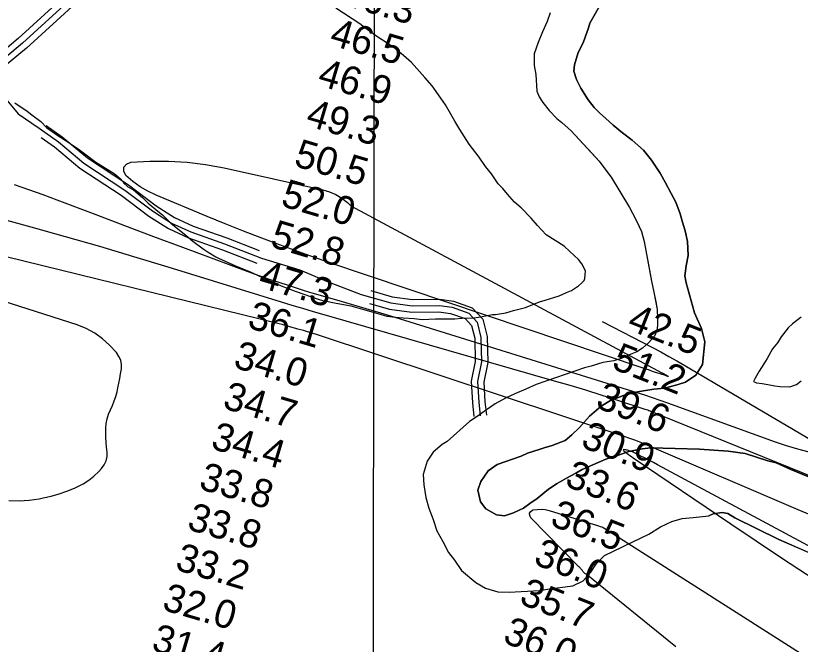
# Model space of a CAD drawing. Extents: x 3192986 to 3230865, y 867483 to 892886.
# Drawn here: x 3212034 to 3213899, y 880283 to 881777 of the extents above; entities that cross this region are included whole.
import ezdxf

# ---------------------------------------------------------------- set-up
doc = ezdxf.new("R2010")
doc.units = 0
for name, color, linetype in [('V-GRID-MAJR', 7, 'Continuous'), ('V-RIVR-RANG', 7, 'Continuous'), ('V-ROAD-CNTR', 7, 'Continuous'), ('V-SITE-VEGE', 7, 'Continuous'), ('V-TOPO-MAJR', 7, 'Continuous'), ('V-TOPO-MINR', 7, 'Continuous'), ('V-TOPO-SHOR', 7, 'Continuous')]:
    doc.layers.add(name, color=color, linetype=linetype)

msp = doc.modelspace()

# ---------------------------------------------------------------- linework, layer by layer
at = {"layer": 'V-GRID-MAJR'}
msp.add_spline([(3212870.4, 872891.2), (3212881.9, 878950.4), (3212893.3, 885013.1), (3212904.8, 891075.8), (3212904.8, 891079.2)], degree=3, dxfattribs=at)
at = {"layer": 'V-ROAD-CNTR'}
for points in [[(3212546.2, 882171.5), (3212450.8, 882086.8), (3212324.9, 881977.5), (3212156.6, 881829.2), (3212040.1, 881722.5), (3211954.9, 881651.4), (3211923.3, 881628.9)], [(3212166.6, 881818.1), (3212049.9, 881711.2), (3211964.1, 881639.5), (3211897.6, 881592.2), (3211798.6, 881545.3), (3211684.7, 881510.3), (3211599.3, 881496.3), (3211553.9, 881489.8), (3211525.1, 881494.2), (3211518, 881509.3), (3211515.9, 881530.1), (3211524.6, 881534.2), (3211547.8, 881535.8), (3211573.7, 881526.2), (3211590.7, 881514.1), (3211603.3, 881507), (3211620.1, 881498.4)], [(3212176.7, 881806.9), (3212059.8, 881699.9), (3212000.6, 881650.5)], [(3212013.3, 881576.2), (3212039.6, 881543.7), (3212089.7, 881509.4), (3212135.6, 881477.1), (3212195.9, 881426.7), (3212293.2, 881362.4), (3212359.3, 881313.1), (3212404.3, 881284.1), (3212450.4, 881263), (3212530.6, 881234.6), (3212618.5, 881200.7), (3212709.2, 881172.7), (3212772.6, 881145.7), (3212855, 881114.7), (3212925.6, 881094.5), (3212976.5, 881087.5), (3213041.2, 881088.4), (3213071.2, 881084), (3213110.8, 881070), (3213131, 881048.5), (3213140, 881012.3), (3213141.1, 880954.2), (3213131.9, 880907.3), (3213134.6, 880858.4), (3213138.2, 880825.9)], [(3212106.4, 881515.9), (3212144.7, 881489), (3212204.9, 881438.8), (3212301.8, 881374.6), (3212367.8, 881325.4), (3212411.6, 881297.3), (3212456.1, 881277), (3212535.8, 881248.7), (3212612.8, 881218.9)], [(3212094.5, 881487.6), (3212126.5, 881465.1), (3212186.9, 881414.7), (3212284.6, 881350.1), (3212350.7, 881300.8), (3212397.1, 881270.9), (3212444.8, 881249.1), (3212525.3, 881220.6), (3212607.6, 881188.8)], [(3212878.4, 881123.6), (3212928.7, 881109.2), (3212977.5, 881102.5), (3213042.2, 881103.4), (3213074.8, 881098.7), (3213119.2, 881082.9), (3213144.6, 881056), (3213154.9, 881014.3), (3213156.2, 880952.9), (3213147, 880906.3), (3213149.5, 880859.7), (3213153.1, 880827.6)], [(3212875.2, 881093.3), (3212922.5, 881079.8), (3212975.6, 881072.5), (3213040.2, 881073.4), (3213067.6, 881069.4), (3213102.3, 881057), (3213117.4, 881041.1), (3213125, 881010.3), (3213126.1, 880955.5), (3213116.8, 880908.4), (3213119.6, 880857.2), (3213123.2, 880824.3)]]:
    msp.add_lwpolyline(points, dxfattribs=at)
at = {"layer": 'V-SITE-VEGE'}
for p, q in [((3212852, 881757.4), (3212795, 881794.9)), ((3213304.2, 881783.7), (3213297.2, 881762.6)), ((3212869.7, 881743.9), (3212852, 881757.4)), ((3213297.2, 881762.6), (3213286.2, 881738.3)), ((3212894.8, 881725.7), (3212869.7, 881743.9)), ((3213286.2, 881738.3), (3213275.9, 881712.8)), ((3212912.6, 881715), (3212894.8, 881725.7)), ((3212936.8, 881697.7), (3212912.6, 881715)), ((3213275.9, 881712.8), (3213266.8, 881686.1)), ((3212955.5, 881682.4), (3212936.8, 881697.7)), ((3212975, 881665.2), (3212955.5, 881682.4)), ((3213266.8, 881686.1), (3213266.6, 881658.5)), ((3213006.5, 881629.8), (3212975, 881665.2)), ((3213266.6, 881658.5), (3213270.2, 881637.4)), ((3213270.2, 881637.4), (3213273.1, 881597.3)), ((3213024.2, 881609.8), (3213006.5, 881629.8)), ((3213044.5, 881581.2), (3213024.2, 881609.8)), ((3213055.6, 881565.1), (3213044.5, 881581.2)), ((3213273.1, 881597.3), (3213278.4, 881583.9)), ((3213278.4, 881583.9), (3213287.2, 881570.4)), ((3212032.3, 881569.4), (3212061.3, 881550.1)), ((3213077.6, 881526.1), (3213055.6, 881565.1)), ((3213287.2, 881570.4), (3213302.1, 881551.9)), ((3212061.3, 881550.1), (3212072.4, 881541.5)), ((3213302.1, 881551.9), (3213320.5, 881532.8)), ((3212072.4, 881541.5), (3212093.9, 881525.2)), ((3212093.9, 881525.2), (3212106.9, 881510.8)), ((3213089.6, 881506.2), (3213077.6, 881526.1)), ((3213320.5, 881532.8), (3213332.1, 881523.2)), ((3213332.1, 881523.2), (3213354, 881503.5)), ((3212106.9, 881510.8), (3212132.1, 881493.5)), ((3213111.7, 881471.9), (3213089.6, 881506.2)), ((3212132.1, 881493.5), (3212151.7, 881481)), ((3213354, 881503.5), (3213421, 881431.2)), ((3212151.7, 881481), (3212182.5, 881460.8)), ((3213135.7, 881440.5), (3213111.7, 881471.9)), ((3212182.5, 881460.8), (3212198.3, 881448.3)), ((3212198.3, 881448.3), (3212224.4, 881429.1)), ((3213150.5, 881418.6), (3213135.7, 881440.5)), ((3213421, 881431.2), (3213434.2, 881412.9)), ((3212224.4, 881429.1), (3212241.2, 881418.4)), ((3212241.2, 881418.4), (3212268.3, 881402)), ((3213165.3, 881401.4), (3213150.5, 881418.6)), ((3213434.2, 881412.9), (3213449.5, 881393.2)), ((3212268.3, 881402), (3212282.3, 881389.6)), ((3213181, 881377.6), (3213165.3, 881401.4)), ((3213449.5, 881393.2), (3213493, 881321.4)), ((3212282.3, 881389.6), (3212288.8, 881382.9)), ((3212288.8, 881382.9), (3212290.6, 881380)), ((3212290.6, 881380), (3212300.8, 881370.5)), ((3213192.1, 881366.2), (3213181, 881377.6)), ((3212300.8, 881370.5), (3212313.9, 881362.8)), ((3212313.9, 881362.8), (3212335.3, 881344.5)), ((3213203.3, 881352.8), (3213192.1, 881366.2)), ((3212335.3, 881344.5), (3212349.3, 881331.2)), ((3213220, 881333.7), (3213203.3, 881352.8)), ((3212349.3, 881331.2), (3212371.6, 881312)), ((3213235.8, 881320.3), (3213220, 881333.7)), ((3213259, 881295.5), (3213235.8, 881320.3)), ((3213493, 881321.4), (3213500.5, 881307.4)), ((3212371.6, 881312), (3212382.8, 881303.3)), ((3212382.8, 881303.3), (3212403.2, 881284.2)), ((3213500.5, 881307.4), (3213510.4, 881288.1)), ((3212403.2, 881284.2), (3212439.6, 881254.5)), ((3213274.7, 881278.3), (3213259, 881295.5)), ((3213510.4, 881288.1), (3213521.3, 881264.1)), ((3213295.2, 881256.3), (3213274.7, 881278.3)), ((3213521.3, 881264.1), (3213528.2, 881240.3)), ((3212439.6, 881254.5), (3212455.4, 881241.1)), ((3213338.1, 881229.3), (3213295.2, 881256.3)), ((3212455.4, 881241.1), (3212479.6, 881222.8)), ((3213351.1, 881216.9), (3213338.1, 881229.3)), ((3213528.2, 881240.3), (3213545.6, 881146.4)), ((3212479.6, 881222.8), (3212491.8, 881215.1)), ((3212491.8, 881215.1), (3212509.5, 881203.5)), ((3213371.6, 881197.8), (3213351.1, 881216.9)), ((3212509.5, 881203.5), (3212516.1, 881200.6)), ((3212516.1, 881200.6), (3212556.3, 881182.1)), ((3213379.9, 881187.3), (3213371.6, 881197.8)), ((3212556.3, 881182.1), (3212591, 881168.4)), ((3213388.2, 881170.2), (3213379.9, 881187.3)), ((3213388, 881160.8), (3213388.2, 881170.2)), ((3212591, 881168.4), (3212619.1, 881155.8)), ((3212619.1, 881155.8), (3212664.9, 881135.3)), ((3213385, 881147.6), (3213387, 881152.3)), ((3213387, 881152.3), (3213388, 881160.8)), ((3212664.9, 881135.3), (3212698.7, 881122.6)), ((3213355.4, 881123.6), (3213371.6, 881134.6)), ((3213371.6, 881134.6), (3213379.3, 881141.1)), ((3213379.3, 881141.1), (3213385, 881147.6)), ((3213545.6, 881146.4), (3213551.2, 881119.7)), ((3212698.7, 881122.6), (3212737.1, 881108.9)), ((3213326.1, 881110.8), (3213343.1, 881119)), ((3213343.1, 881119), (3213355.4, 881123.6)), ((3213551.2, 881119.7), (3213559.1, 881079.1)), ((3212737.1, 881108.9), (3212753.1, 881103)), ((3212753.1, 881103), (3212763.4, 881100)), ((3212763.4, 881100), (3212772.8, 881098.9)), ((3212772.8, 881098.9), (3212791.6, 881094.9)), ((3212791.6, 881094.9), (3212831, 881087.7)), ((3213245.6, 881083.7), (3213278.7, 881097.3)), ((3213278.7, 881097.3), (3213292.9, 881100.9)), ((3213292.9, 881100.9), (3213312.8, 881107.2)), ((3213312.8, 881107.2), (3213326.1, 881110.8)), ((3212831, 881087.7), (3212858.2, 881079.8)), ((3212858.2, 881079.8), (3212894.8, 881068.9)), ((3213199.2, 881071.1), (3213217.2, 881076.5)), ((3213217.2, 881076.5), (3213245.6, 881083.7)), ((3213559.1, 881079.1), (3213559.5, 881057.2)), ((3212894.8, 881068.9), (3212916.4, 881063)), ((3212916.4, 881063), (3212937.1, 881060.8)), ((3212937.1, 881060.8), (3212955, 881058.6)), ((3212955, 881058.6), (3212981.4, 881057.3)), ((3212981.4, 881057.3), (3213000.2, 881055.2)), ((3213051.1, 881056.3), (3213077.5, 881056.9)), ((3213077.5, 881056.9), (3213094.5, 881058.5)), ((3213094.5, 881058.5), (3213123.7, 881059)), ((3213123.7, 881059), (3213138.8, 881061.6)), ((3213138.8, 881061.6), (3213167.1, 881066.9)), ((3213167.1, 881066.9), (3213174.7, 881066.8)), ((3213174.7, 881066.8), (3213199.2, 881071.1)), ((3213559.5, 881057.2), (3213559.2, 881041.7)), ((3213000.2, 881055.2), (3213032.2, 881056.6)), ((3213032.2, 881056.6), (3213051.1, 881056.3)), ((3213559.2, 881041.7), (3213557.6, 881028.4)), ((3213557.6, 881028.4), (3213552.2, 881015.2)), ((3213552.2, 881015.2), (3213539, 881000)), ((3213524, 880986.5), (3213510.1, 880978.4)), ((3213539, 881000), (3213524, 880986.5)), ((3213490.4, 880970.1), (3213473.2, 880962.4)), ((3213510.1, 880978.4), (3213490.4, 880970.1)), ((3213429.8, 880952.9), (3213401.6, 880943.8)), ((3213455.8, 880957.1), (3213429.8, 880952.9)), ((3213473.2, 880962.4), (3213455.8, 880957.1)), ((3213386.2, 880940.2), (3213271.3, 880900.5)), ((3213401.6, 880943.8), (3213386.2, 880940.2)), ((3213246.6, 880889.3), (3213220.8, 880878.6)), ((3213271.3, 880900.5), (3213246.6, 880889.3)), ((3213220.8, 880878.6), (3213198.6, 880868)), ((3213173.4, 880854.8), (3213153.1, 880840.1)), ((3213198.6, 880868), (3213173.4, 880854.8)), ((3213153.1, 880840.1), (3213131.1, 880824.8)), ((3213131.1, 880824.8), (3213112.4, 880812.9)), ((3213112.4, 880812.9), (3213059.6, 880765.1)), ((3213059.6, 880765.1), (3213048.1, 880758.1)), ((3213048.1, 880758.1), (3213026.1, 880739.6)), ((3213026.1, 880739.6), (3213012.3, 880718.2)), ((3213012.3, 880718.2), (3213002.8, 880686.5)), ((3213002.8, 880686.5), (3213004.1, 880661.9)), ((3213004.1, 880661.9), (3213008.7, 880632.3)), ((3213008.7, 880632.3), (3213016.1, 880607.1)), ((3213016.1, 880607.1), (3213026.3, 880580.1)), ((3213681.2, 880588.4), (3213691.9, 880593.4)), ((3213691.9, 880593.4), (3213713.1, 880596.1)), ((3213713.1, 880596.1), (3213726.4, 880594.1)), ((3213726.4, 880594.1), (3213743.7, 880583.9)), ((3213026.3, 880580.1), (3213034.9, 880552.5)), ((3213566.8, 880562.2), (3213593.6, 880575.4)), ((3213593.6, 880575.4), (3213618.1, 880582)), ((3213618.1, 880582), (3213644.4, 880584.5)), ((3213644.4, 880584.5), (3213681.2, 880588.4)), ((3213743.7, 880583.9), (3213847.8, 880532.4)), ((3213539, 880545), (3213566.8, 880562.2)), ((3213034.9, 880552.5), (3213049.5, 880527.5)), ((3213433.9, 880494.2), (3213520.8, 880536)), ((3213520.8, 880536), (3213539, 880545)), ((3213049.5, 880527.5), (3213063, 880501.7)), ((3213847.8, 880532.4), (3213989.3, 880470.5)), ((3213063, 880501.7), (3213076.9, 880483.2)), ((3213076.9, 880483.2), (3213094, 880459)), ((3213414.4, 880475.1), (3213433.9, 880494.2)), ((3213401.1, 880454.5), (3213414.4, 880475.1)), ((3213094, 880459), (3213127.5, 880429.9)), ((3213383, 880434.4), (3213401.1, 880454.5)), ((3213127.5, 880429.9), (3213150.9, 880416.5)), ((3213358.1, 880422.2), (3213383, 880434.4)), ((3213150.9, 880416.5), (3213179.8, 880408.3)), ((3213179.8, 880408.3), (3213207.2, 880407.2)), ((3213207.2, 880407.2), (3213279, 880410.9)), ((3213279, 880410.9), (3213302.8, 880414.7)), ((3213302.8, 880414.7), (3213327.1, 880418.2)), ((3213327.1, 880418.2), (3213358.1, 880422.2))]:
    msp.add_line(p, q, dxfattribs=at)
for points in [[(3213430.9, 881816.5), (3213398.9, 881759.4), (3213395.5, 881748.2), (3213382.6, 881712), (3213370.7, 881689.4), (3213362.3, 881659.9), (3213360.9, 881645.1), (3213367, 881625.5), (3213377.1, 881604.5), (3213394.7, 881576.7), (3213409.2, 881558.5), (3213422.2, 881545.1), (3213436, 881533.3), (3213454.2, 881517), (3213476.7, 881498.3), (3213499.7, 881480.8), (3213526.5, 881457.2), (3213545.4, 881433.7), (3213565.7, 881402.6), (3213578.6, 881379.7), (3213592.2, 881354.3), (3213603.2, 881333.7), (3213613.2, 881306.4), (3213619.3, 881286.3), (3213625, 881265.4), (3213630.6, 881240.1), (3213632.5, 881207.3), (3213627.8, 881182.2), (3213624.6, 881159), (3213628, 881141.8), (3213647.8, 881070.7), (3213664.4, 881033.3), (3213672.4, 881001.6), (3213666.4, 880948.1), (3213650.4, 880922.7), (3213626.2, 880906.3), (3213608.5, 880900.5), (3213576.4, 880892.2)], [(3213901.4, 881060.3), (3213894, 881054.8), (3213880.1, 881044.9), (3213869.8, 881035), (3213853.9, 881014.1), (3213844.5, 880999.5), (3213833.3, 880985), (3213820.1, 880962.2), (3213812.6, 880949.5), (3213801.3, 880932.2), (3213794.7, 880921.2), (3213791, 880914), (3213788.1, 880907.6), (3213794.5, 880904.7), (3213808.2, 880902.7), (3213830.2, 880898.7), (3213838.5, 880897.7), (3213850.4, 880895.7), (3213874.3, 880895.3), (3213890, 880900.6), (3213901.1, 880909.6)], [(3213576.4, 880892.2), (3213550.8, 880889.4), (3213517.1, 880884.2), (3213489, 880878.2), (3213447.6, 880862.4), (3213425.8, 880848.8), (3213397.9, 880825.2), (3213373.9, 880798.7), (3213356.1, 880780.6), (3213339.9, 880767.6), (3213309.3, 880755.6), (3213290.4, 880749.9), (3213278.4, 880746.5), (3213250.3, 880737.7), (3213235.8, 880730.3), (3213178.3, 880710.7), (3213156.9, 880695.5), (3213139.7, 880670.1), (3213132.6, 880649.8), (3213138.6, 880622.1), (3213151.2, 880605.1), (3213177, 880590.8), (3213195.7, 880588.9), (3213217, 880595.4), (3213230.7, 880602), (3213240.8, 880607.1), (3213256.5, 880617.6), (3213273.9, 880629.8), (3213300.2, 880652.2), (3213320.8, 880665.5), (3213343, 880678), (3213365.5, 880689.7), (3213380.9, 880698.2), (3213406.2, 880709.5), (3213436.4, 880723), (3213462.5, 880731.1), (3213491.5, 880741.4), (3213523.2, 880747.8), (3213543.6, 880750.3), (3213659.1, 880746.6), (3213727.4, 880742.4), (3213767.7, 880736.3), (3213821.5, 880719.5), (3213841.4, 880714.4), (3213876.8, 880698.3), (3213916.9, 880682.1)]]:
    msp.add_lwpolyline(points, dxfattribs=at)
at = {"layer": 'V-TOPO-MAJR'}
for points in [[(3213994.4, 880560.6), (3213893.6, 880602.5), (3213535.1, 880756.5), (3213521.6, 880762.1), (3213507.9, 880767.5), (3213494.1, 880772.5), (3213480.2, 880777.3), (3212748.8, 881019), (3212741.1, 881021.5), (3212733.4, 881023.9), (3212725.6, 881026.2), (3212717.9, 881028.5), (3212704.7, 881032.2), (3212700, 881033.6), (3212688.3, 881036.9), (3212681.3, 881038.9), (3212674.2, 881040.8), (3212667.2, 881042.7), (3212660.1, 881044.5), (3211923.4, 881225.1)], [(3213602.9, 880277.5), (3213389.7, 880449.6), (3213387.2, 880451.8), (3213384.7, 880454.1), (3213382.4, 880456.5), (3213380.2, 880459.1), (3213376.9, 880463.2), (3213376.4, 880463.7), (3213375.4, 880464.9), (3213373.4, 880467.2), (3213372.9, 880467.7), (3213258.3, 880583.6), (3213255.8, 880589.4), (3213255.5, 880594.5), (3213258.5, 880598.8), (3213263.6, 880602.4), (3213273.2, 880603.9), (3213282.8, 880604.4), (3213292.3, 880603.4), (3213301.7, 880601.2), (3213419.3, 880564.8), (3213423.2, 880563.5), (3213427, 880562), (3213430.8, 880560.4), (3213434.6, 880558.7), (3214442.8, 879916.2)]]:
    msp.add_lwpolyline(points, dxfattribs=at)
at = {"layer": 'V-TOPO-MINR'}
for points in [[(3213584.8, 880920), (3213584.6, 880919.9), (3213584.4, 880919.8), (3213583.4, 880920), (3213581.4, 880920.5), (3213580.5, 880920.9), (3213576.1, 880922.4), (3213572.9, 880923.5), (3213569.7, 880924.6), (3213566.6, 880925.7), (3213563.4, 880926.7), (3213555, 880929.4), (3213547.7, 880931.8), (3213540.3, 880934.3), (3213533, 880936.7), (3213525.7, 880939.2), (3212778.6, 881190.6), (3212765, 881195.2), (3212751.5, 881199.9), (3212738, 881204.6), (3212724.5, 881209.5), (3212663.3, 881231.7), (3212619.4, 881248), (3212575.7, 881264.7), (3212532.1, 881282), (3212488.8, 881299.7), (3212367.7, 881350.2), (3212348.2, 881359.6), (3212329.6, 881370.3), (3212312.3, 881383), (3212295.8, 881397), (3212291.3, 881407.7), (3212291.2, 881416.9), (3212297.3, 881423.7), (3212307.7, 881428.9), (3212353.1, 881430.9), (3212397.5, 881431.1), (3212441.7, 881428.9), (3212485.5, 881423.3), (3212529.2, 881415.4), (3212764.1, 881363.1), (3212780.1, 881358.2), (3212795.3, 881351.8), (3212809.2, 881343), (3212822.4, 881332.8), (3212830.4, 881325.4), (3213570, 880928.3), (3213570.5, 880928.1), (3213571.5, 880927.6), (3213572, 880927.3), (3213584.6, 880920.4), (3213584.8, 880920.2), (3213584.8, 880920)], [(3213920.2, 880739.9), (3213893.2, 880746.7), (3213866.5, 880754.8), (3213840, 880763.7), (3213583.8, 880856.3), (3213565.8, 880862.7), (3213547.8, 880868.9), (3213529.7, 880874.8), (3213511.6, 880880.6), (3212936.1, 881059.5), (3212901.6, 881070.1), (3212867, 881080.5), (3212832.4, 881090.8), (3212797.7, 881100.9), (3212738.6, 881117.9), (3212733.4, 881119.5), (3212728.3, 881121), (3212723.1, 881122.6), (3212718, 881124.2), (3212682.8, 881135.4), (3212660.1, 881142.7), (3212637.6, 881150.3), (3212615.1, 881158.1), (3212592.6, 881166.2), (3212499.8, 881200.3), (3212431, 881225.7), (3212362.4, 881251.3), (3212293.8, 881277.2), (3212225.3, 881303.3), (3212133, 881338.7), (3212099.3, 881351.3), (3212065.4, 881363.4), (3212031.4, 881374.9)], [(3213931.4, 880679.2), (3213541.9, 880837.2), (3213539, 880838.3), (3213536.2, 880839.3), (3213533.3, 880840.4), (3213530.4, 880841.3), (3213462.7, 880863.4), (3213425.9, 880875.2), (3213389, 880886.8), (3213352, 880897.9), (3213314.9, 880908.8), (3212767.1, 881066.1), (3212741.8, 881073.4), (3212716.5, 881080.9), (3212691.2, 881088.5), (3212666, 881096.2), (3212396.3, 881179.4), (3212315.2, 881204), (3212234, 881228.1), (3212152.6, 881251.5), (3212071, 881274.3), (3211931.5, 881312.7)], [(3212042, 880624.1), (3212066, 880625.9), (3212090.1, 880629.2), (3212099.5, 880631), (3212118.6, 880635.3), (3212137.3, 880640.5), (3212155.7, 880647), (3212173.7, 880654.4), (3212180, 880657.3), (3212194.2, 880664.7), (3212207.6, 880673.1), (3212220.1, 880683), (3212231.8, 880693.9), (3212238.2, 880700.6), (3212244.6, 880709.4), (3212249.2, 880718.9), (3212251.1, 880729.2), (3212251.1, 880740.1), (3212249.9, 880751.6), (3212248.9, 880763.1), (3212248.5, 880774.6), (3212248.4, 880786.1), (3212248.5, 880796.8), (3212249.5, 880808.1), (3212251.4, 880819.2), (3212254.9, 880829.9), (3212259.3, 880840.4), (3212264.2, 880850.8), (3212268.5, 880861.4), (3212272, 880872.3), (3212274.9, 880883.4), (3212277, 880892.9), (3212279.3, 880904), (3212281.5, 880915.1), (3212283.5, 880926.2), (3212285.4, 880937.4), (3212285.5, 880948), (3212283.9, 880958.1), (3212279.6, 880967.4), (3212273.4, 880976.2), (3212256.9, 880993.8), (3212240, 881009.3), (3212221.8, 881022.8), (3212201.7, 881033.4), (3212180.5, 881042.1), (3211906.8, 881129.5)], [(3213428, 881050.6), (3213547.8, 880988.1), (3213567.2, 880977.8), (3213586.4, 880967.3), (3213605.6, 880956.5), (3213624.6, 880945.5), (3213954.2, 880751.6)], [(3214612.4, 880144.9), (3213559.9, 880710), (3213549.7, 880715.4), (3213539.3, 880720.8), (3213529, 880726), (3213518.5, 880731.2), (3213498.3, 880741.1), (3213497.3, 880741.5), (3213497, 880741.6), (3213488.5, 880744.3), (3213486.4, 880744.9), (3213484.2, 880745.3), (3213479.7, 880745.9), (3213478.8, 880745.5), (3213478.3, 880745), (3213478.4, 880744.2), (3213478.8, 880743.4), (3213486.4, 880737.6), (3213490.2, 880734.8), (3213494, 880732), (3213497.9, 880729.3), (3213501.8, 880726.6), (3213733.8, 880569.4), (3213854.3, 880488.9), (3213975.5, 880409.6)], [(3212017.8, 880624.6), (3212042, 880624.1)]]:
    msp.add_lwpolyline(points, dxfattribs=at)
at = {"layer": 'V-TOPO-SHOR'}
for points in [[(3213447.6, 880862.4), (3213489, 880878.2), (3213517.1, 880884.2), (3213550.8, 880889.4), (3213576.4, 880892.2), (3213608.5, 880900.5), (3213626.2, 880906.3), (3213650.4, 880922.7), (3213666.4, 880948.1), (3213672.4, 881001.6), (3213664.4, 881033.3), (3213647.8, 881070.7), (3213628, 881141.8), (3213624.6, 881159), (3213627.8, 881182.2), (3213632.5, 881207.3), (3213630.6, 881240.1), (3213625, 881265.4), (3213619.3, 881286.3), (3213613.2, 881306.4), (3213603.2, 881333.7), (3213592.2, 881354.3), (3213578.6, 881379.7), (3213565.7, 881402.6), (3213545.4, 881433.7), (3213526.5, 881457.2), (3213499.7, 881480.8), (3213476.7, 881498.3), (3213454.2, 881517), (3213436, 881533.3), (3213422.2, 881545.1), (3213409.2, 881558.5), (3213394.7, 881576.7), (3213377.1, 881604.5), (3213367, 881625.5), (3213360.9, 881645.1), (3213362.3, 881659.9), (3213370.7, 881689.4), (3213382.6, 881712), (3213395.5, 881748.2), (3213398.9, 881759.4), (3213430.9, 881816.5)], [(3213304.2, 881783.7), (3213297.2, 881762.6), (3213286.2, 881738.3), (3213275.9, 881712.8), (3213266.8, 881686.1), (3213266.6, 881658.5), (3213270.2, 881637.4)], [(3213270.2, 881637.4), (3213273.1, 881597.3), (3213278.4, 881583.9), (3213287.2, 881570.4), (3213302.1, 881551.9), (3213320.5, 881532.8), (3213332.1, 881523.2), (3213354, 881503.5), (3213404.5, 881449), (3213421, 881431.2), (3213434.2, 881412.9), (3213449.5, 881393.2), (3213493, 881321.4), (3213500.5, 881307.4), (3213510.4, 881288.1), (3213521.3, 881264.1), (3213528.2, 881240.3), (3213542.4, 881163.4), (3213545.6, 881146.4), (3213551.2, 881119.7), (3213555.6, 881097.1), (3213559.1, 881079.1), (3213559.5, 881057.2), (3213559.2, 881041.7), (3213557.6, 881028.4), (3213552.2, 881015.2), (3213539, 881000), (3213524, 880986.5), (3213510.1, 880978.4), (3213490.4, 880970.1), (3213473.2, 880962.4), (3213455.8, 880957.1), (3213429.8, 880952.9), (3213401.6, 880943.8), (3213386.2, 880940.2), (3213271.3, 880900.5), (3213246.6, 880889.3), (3213220.8, 880878.6), (3213198.6, 880868), (3213173.4, 880854.8), (3213153.1, 880840.1), (3213131.1, 880824.8), (3213112.4, 880812.9), (3213059.6, 880765.1), (3213048.1, 880758.1), (3213026.1, 880739.6), (3213012.3, 880718.2), (3213002.8, 880686.5), (3213004.1, 880661.9), (3213008.7, 880632.3), (3213016.1, 880607.1), (3213026.3, 880580.1), (3213034.9, 880552.5), (3213049.5, 880527.5), (3213063, 880501.7), (3213076.9, 880483.2), (3213094, 880459), (3213127.5, 880429.9), (3213150.9, 880416.5), (3213179.8, 880408.3), (3213207.2, 880407.2), (3213279, 880410.9), (3213302.8, 880414.7), (3213327.1, 880418.2), (3213358.1, 880422.2), (3213383, 880434.4), (3213401.1, 880454.5), (3213414.4, 880475.1), (3213433.9, 880494.2), (3213520.8, 880536), (3213539, 880545), (3213566.8, 880562.2), (3213593.6, 880575.4), (3213618.1, 880582), (3213644.4, 880584.5), (3213681.2, 880588.4)], [(3213916.9, 880682.1), (3213876.8, 880698.3), (3213841.4, 880714.4), (3213821.5, 880719.5), (3213767.7, 880736.3), (3213727.4, 880742.4), (3213659.1, 880746.6), (3213543.6, 880750.3), (3213523.2, 880747.8), (3213491.5, 880741.4), (3213462.5, 880731.1), (3213436.4, 880723), (3213406.2, 880709.5), (3213380.9, 880698.2), (3213365.5, 880689.7), (3213343, 880678), (3213320.8, 880665.5), (3213300.2, 880652.2), (3213273.9, 880629.8), (3213256.5, 880617.6), (3213240.8, 880607.1), (3213230.7, 880602), (3213217, 880595.4), (3213195.7, 880588.9), (3213177, 880590.8), (3213151.2, 880605.1), (3213138.6, 880622.1), (3213132.6, 880649.8), (3213139.7, 880670.1), (3213156.9, 880695.4), (3213178.3, 880710.7), (3213235.8, 880730.3), (3213250.3, 880737.7), (3213278.4, 880746.5), (3213290.4, 880749.9), (3213309.3, 880755.6), (3213339.9, 880767.6), (3213356.1, 880780.6), (3213373.9, 880798.7), (3213397.9, 880825.2), (3213425.8, 880848.8), (3213447.6, 880862.4)], [(3213726.4, 880594.1), (3213713.1, 880596.1), (3213691.9, 880593.4), (3213681.2, 880588.4)], [(3213989.3, 880470.5), (3213847.8, 880532.4), (3213743.7, 880583.9), (3213726.4, 880594.1)]]:
    msp.add_lwpolyline(points, dxfattribs=at)

# ---------------------------------------------------------------- texts
at = {"layer": 'V-RIVR-RANG'}
for s, rotation, p in [('46.3', 343.4683, (3212805.5, 881804.4)), ('46.5', 343.4683, (3212777.3, 881708.5)), ('46.9', 343.4683, (3212748.8, 881612.6)), ('49.3', 343.4683, (3212720.8, 881516.6)), ('50.5', 343.4683, (3212692.6, 881420.7)), ('52.0', 343.4683, (3212661.6, 881325.6)), ('52.8', 343.4683, (3212636.2, 881228.8)), ('47.3', 343.4683, (3212608, 881132.9)), ('36.1', 343.4683, (3212582, 881036.3)), ('42.5', 338.3783, (3213484.5, 881032.5)), ('34.0', 343.4683, (3212548.7, 880941.9)), ('51.2', 338.3783, (3213447.9, 880939.4)), ('34.7', 343.4683, (3212523.3, 880845.1)), ('39.6', 338.3783, (3213409.6, 880847.1)), ('34.4', 343.4683, (3212495.1, 880749.2)), ('30.9', 338.3783, (3213374.4, 880753.4)), ('33.8', 343.4683, (3212466.8, 880653.2)), ('33.6', 338.3783, (3213336.3, 880661)), ('33.8', 343.4683, (3212438.6, 880557.3)), ('36.5', 338.3783, (3213301.4, 880567.2)), ('33.2', 343.4683, (3212410.4, 880461.4)), ('36.0', 338.3783, (3213262.1, 880475.2)), ('32.0', 343.4683, (3212379.4, 880366.2)), ('35.7', 338.3783, (3213228.2, 880381.1)), ('31.4', 343.4683, (3212353.9, 880269.5)), ('36.0', 338.3783, (3213188.9, 880289.1))]:
    msp.add_text(s, height=67, rotation=rotation, dxfattribs=at).set_placement(p)

doc.saveas('drawing.dxf')
